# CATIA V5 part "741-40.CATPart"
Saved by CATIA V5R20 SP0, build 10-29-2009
Part number: 741-40
Bounding box of the stored display mesh (mm): x -33 to 33, y -32.999 to 32.999, z -37 to 45
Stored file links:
  C:\Users\Utente\Desktop\IO LAVORO\3D X SITO CF\X SITO\741\741-40.CATPart
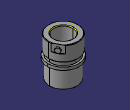
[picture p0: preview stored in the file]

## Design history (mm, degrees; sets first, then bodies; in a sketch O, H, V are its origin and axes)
Set1
  DatumSurface1 to DatumSurface42 "741-40"
Body1 (main body)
